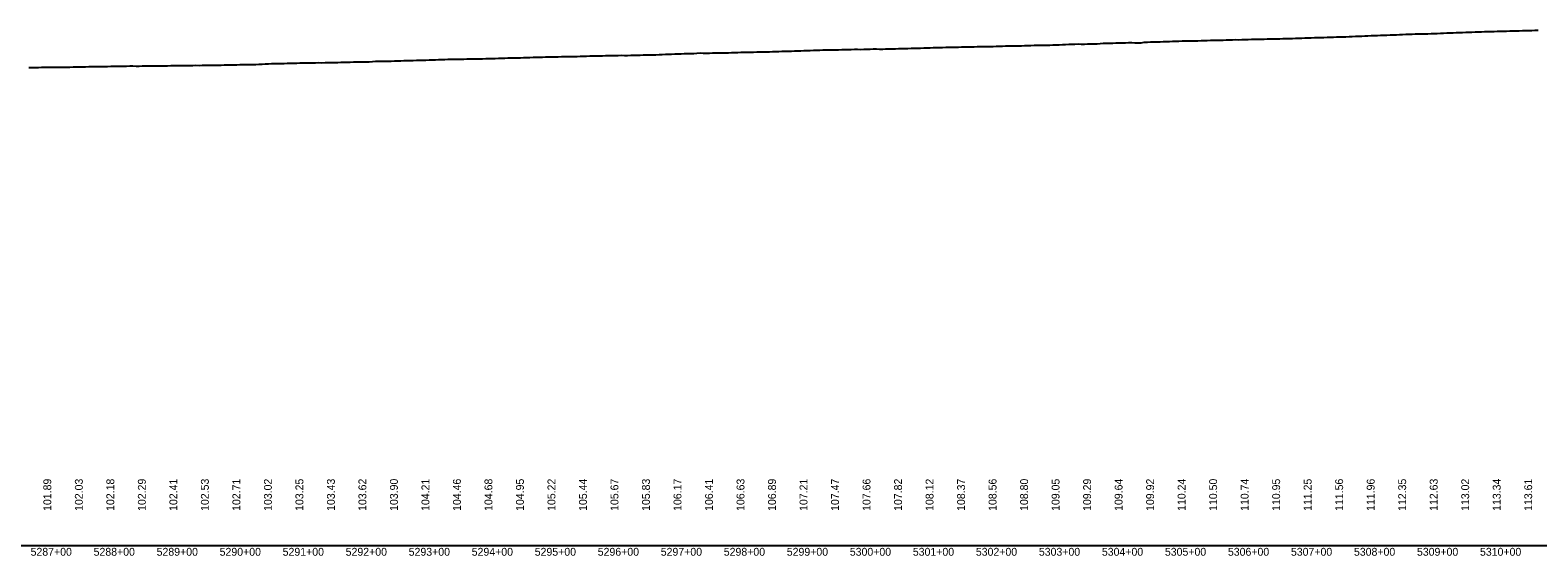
# Model space of a CAD drawing. Extents: x 2147288 to 2220488, y 740833 to 759333.
# Drawn here: x 2161047 to 2163439, y 758067 to 758902 of the extents above; entities that cross this region are included whole.
import ezdxf

# ---------------------------------------------------------------- set-up
doc = ezdxf.new("R2010")
doc.units = 0
for name, color, linetype in [('RD_DDB_Profile_EX', 7, 'Continuous'), ('RD_DDB_StaTX', 7, 'Continuous'), ('RD_DDB_StripGrade', 7, 'Continuous'), ('RD_GPK_Profile_Cell', 7, 'Continuous')]:
    doc.layers.add(name, color=color, linetype=linetype)

msp = doc.modelspace()

# ---------------------------------------------------------------- linework, layer by layer
at = {"layer": 'RD_DDB_Profile_EX'}
for points in [[(2162534.6, 758875.3), (2162539.6, 758875.4), (2162544.6, 758875.4), (2162549.6, 758875.5), (2162554.6, 758875.6), (2162559.6, 758875.8), (2162564.6, 758875.9), (2162569.6, 758875.9), (2162574.6, 758876), (2162579.6, 758876.2), (2162584.6, 758876.4), (2162589.6, 758876.4), (2162594.6, 758876.6), (2162599.6, 758876.7), (2162604.6, 758876.8), (2162609.6, 758876.8), (2162614.6, 758876.9), (2162619.6, 758877), (2162624.6, 758877.2), (2162629.6, 758877.4), (2162634.6, 758877.5), (2162639.6, 758877.6), (2162644.6, 758877.7), (2162649.6, 758877.8), (2162654.6, 758877.9), (2162659.6, 758878), (2162664.6, 758878.1), (2162669.6, 758878.3), (2162674.6, 758878.4), (2162679.6, 758878.6), (2162684.6, 758878.8), (2162689.6, 758879), (2162694.6, 758879.2), (2162699.6, 758879.4), (2162704.6, 758879.6), (2162709.6, 758879.8), (2162714.6, 758879.7), (2162719.6, 758879.7), (2162724.6, 758879.8), (2162729.6, 758879.8), (2162734.6, 758879.9), (2162739.6, 758880.1), (2162744.6, 758880.7), (2162749.6, 758881), (2162754.6, 758880.9), (2162759.6, 758881.1), (2162764.6, 758881.3), (2162769.6, 758881.4), (2162774.6, 758881.5), (2162779.6, 758881.6), (2162784.6, 758881.7), (2162789.6, 758882), (2162794.6, 758881.9), (2162799.6, 758881.7), (2162804.6, 758881.8), (2162809.6, 758881.8), (2162814.6, 758882.6), (2162819.6, 758882.7), (2162824.6, 758882.9), (2162829.6, 758883), (2162834.6, 758883.1), (2162839.6, 758883.3), (2162844.6, 758883.5), (2162849.6, 758883.7), (2162854.6, 758883.8), (2162859.6, 758884), (2162864.6, 758884.2), (2162869.6, 758884.3), (2162874.6, 758884.5), (2162879.6, 758884.6), (2162884.6, 758884.7), (2162889.6, 758884.8), (2162894.6, 758884.9), (2162899.6, 758885), (2162904.6, 758885.1), (2162909.6, 758885.2), (2162914.6, 758885.4), (2162919.6, 758885.6), (2162924.6, 758885.8), (2162929.6, 758885.9), (2162934.6, 758886), (2162939.6, 758886), (2162944.6, 758886.1), (2162949.6, 758886.2), (2162954.6, 758886.4), (2162959.6, 758886.6), (2162964.6, 758886.5), (2162969.6, 758886.8), (2162974.6, 758887), (2162979.6, 758887.1), (2162984.6, 758887.2), (2162989.6, 758887.2), (2162994.6, 758887.2), (2162999.6, 758887.3), (2163004.6, 758887.6), (2163009.6, 758887.7), (2163014.6, 758887.8), (2163019.6, 758887.9), (2163024.6, 758888), (2163029.6, 758888.1), (2163034.6, 758888.3)], [(2163034.6, 758888.3), (2163039.6, 758888.4), (2163044.6, 758888.6), (2163049.6, 758888.7), (2163054.6, 758888.9), (2163059.6, 758889), (2163064.6, 758889.1), (2163069.6, 758889.3), (2163074.6, 758889.4), (2163079.6, 758889.6), (2163084.6, 758889.8), (2163089.6, 758890.1), (2163094.6, 758890.1), (2163099.6, 758890.3), (2163104.6, 758890.4), (2163109.6, 758890.6), (2163114.6, 758890.7), (2163119.6, 758890.9), (2163124.6, 758891), (2163129.6, 758891.2), (2163134.6, 758891.3), (2163139.6, 758891.5), (2163144.6, 758891.7), (2163149.6, 758891.9), (2163154.6, 758891.9), (2163159.6, 758892), (2163164.6, 758892.6), (2163169.6, 758892.8), (2163174.6, 758893), (2163179.6, 758893.2), (2163184.6, 758893.4), (2163189.6, 758893.6), (2163194.6, 758893.8), (2163199.6, 758894), (2163204.6, 758894.2), (2163209.6, 758894.4), (2163214.6, 758894.5), (2163219.6, 758894.7), (2163224.6, 758894.9), (2163229.6, 758895.1), (2163234.6, 758895.3), (2163239.6, 758895.5), (2163244.6, 758895.6), (2163249.6, 758895.8), (2163254.6, 758895.9), (2163259.6, 758896), (2163264.6, 758896.1), (2163269.6, 758896.2), (2163274.6, 758896.3), (2163279.6, 758896.5), (2163284.6, 758896.7), (2163289.6, 758896.9), (2163294.6, 758897.2), (2163299.6, 758897.4), (2163304.6, 758897.6), (2163309.6, 758897.8), (2163314.6, 758897.9), (2163319.6, 758898.1), (2163324.6, 758898.3), (2163329.6, 758898.5), (2163334.6, 758898.7), (2163339.6, 758898.8), (2163344.6, 758899), (2163349.6, 758899.1), (2163354.6, 758899.4), (2163359.6, 758899.5), (2163364.6, 758899.6), (2163369.6, 758899.8), (2163374.6, 758900.1), (2163379.6, 758900.1), (2163384.6, 758900.2), (2163389.6, 758900.3), (2163394.6, 758900.5), (2163399.6, 758900.7), (2163404.6, 758900.7), (2163409.6, 758900.8), (2163414.6, 758900.9), (2163419.6, 758901.1), (2163424.6, 758901.2), (2163429.6, 758901.4), (2163434.6, 758901.6), (2163439.6, 758901.7)], [(2161534.6, 758850.6), (2161539.6, 758850.8), (2161544.6, 758850.9), (2161549.6, 758851), (2161554.6, 758851.1), (2161559.6, 758851.2), (2161564.6, 758851.2), (2161569.6, 758851.2), (2161574.6, 758851.3), (2161579.6, 758851.5), (2161584.6, 758851.6), (2161589.6, 758852.1), (2161594.6, 758852.2), (2161599.6, 758852.3), (2161604.6, 758852.4), (2161609.6, 758852.5), (2161614.6, 758852.6), (2161619.6, 758852.7), (2161624.6, 758852.8), (2161629.6, 758852.9), (2161634.6, 758853), (2161639.6, 758853.3), (2161644.6, 758853.4), (2161649.6, 758853.6), (2161654.6, 758853.7), (2161659.6, 758853.9), (2161664.6, 758854), (2161669.6, 758854.2), (2161674.6, 758854.3), (2161679.6, 758854.4), (2161684.6, 758854.6), (2161689.6, 758854.8), (2161694.6, 758854.9), (2161699.6, 758855.1), (2161704.6, 758855.3), (2161709.6, 758855.4), (2161714.6, 758855.4), (2161719.6, 758855.5), (2161724.6, 758855.6), (2161729.6, 758855.7), (2161734.6, 758855.8), (2161739.6, 758855.9), (2161744.6, 758856), (2161749.6, 758856), (2161754.6, 758856.1), (2161759.6, 758856.2), (2161764.6, 758856.3), (2161769.6, 758856.5), (2161774.6, 758856.6), (2161779.6, 758856.8), (2161784.6, 758856.9), (2161789.6, 758857.1), (2161794.6, 758857.2), (2161799.6, 758857.3), (2161804.6, 758857.5), (2161809.6, 758857.6), (2161814.6, 758857.7), (2161819.6, 758857.9), (2161824.6, 758858), (2161829.6, 758858.1), (2161834.6, 758858.3), (2161839.6, 758858.4), (2161844.6, 758858.6), (2161849.6, 758858.7), (2161854.6, 758858.9), (2161859.6, 758859), (2161864.6, 758859.2), (2161869.6, 758859.3), (2161874.6, 758859.4), (2161879.6, 758859.5), (2161884.6, 758859.6), (2161889.6, 758859.7), (2161894.6, 758859.7), (2161899.6, 758859.8), (2161904.6, 758859.9), (2161909.6, 758860), (2161914.6, 758860.1), (2161919.6, 758860.3), (2161924.6, 758860.5), (2161929.6, 758860.6), (2161934.6, 758860.7), (2161939.6, 758860.8), (2161944.6, 758860.9), (2161949.6, 758861), (2161954.6, 758861), (2161959.6, 758861.2), (2161964.6, 758861.4), (2161969.6, 758861.5), (2161974.6, 758861.6), (2161979.6, 758861.7), (2161984.6, 758861.9), (2161989.6, 758861.4), (2161994.6, 758861.7), (2161999.6, 758862), (2162004.6, 758862.2), (2162009.6, 758862.1), (2162014.6, 758862.2), (2162019.6, 758862.4), (2162024.6, 758862.5), (2162029.6, 758862.7), (2162034.6, 758862.4)], [(2162034.6, 758862.4), (2162039.6, 758862.6), (2162044.6, 758863.1), (2162049.6, 758863.3), (2162054.6, 758863.4), (2162059.6, 758863.6), (2162064.6, 758863.7), (2162069.6, 758863.9), (2162074.6, 758864.1), (2162079.6, 758864.2), (2162084.6, 758864.4), (2162089.6, 758864.5), (2162094.6, 758864.6), (2162099.6, 758864.8), (2162104.6, 758864.9), (2162109.6, 758865.5), (2162114.6, 758865.1), (2162119.6, 758865.2), (2162124.6, 758865.3), (2162129.6, 758865.5), (2162134.6, 758865.6), (2162139.6, 758865.7), (2162144.6, 758865.9), (2162149.6, 758865.9), (2162154.6, 758865.9), (2162159.6, 758866.1), (2162164.6, 758866.3), (2162169.6, 758866.4), (2162174.6, 758866.5), (2162179.6, 758866.6), (2162184.6, 758866.7), (2162189.6, 758866.8), (2162194.6, 758866.9), (2162199.6, 758867.1), (2162204.6, 758867.1), (2162209.6, 758867.2), (2162214.6, 758867.3), (2162219.6, 758867.4), (2162224.6, 758867.6), (2162229.6, 758867.8), (2162234.6, 758868), (2162239.6, 758868.1), (2162244.6, 758868.3), (2162249.6, 758868.4), (2162254.6, 758868.6), (2162259.6, 758868.8), (2162264.6, 758868.9), (2162269.6, 758869.1), (2162274.6, 758869.3), (2162279.6, 758869.4), (2162284.6, 758869.6), (2162289.6, 758869.7), (2162294.6, 758869.9), (2162299.6, 758870), (2162304.6, 758870.2), (2162309.6, 758870.3), (2162314.6, 758870.5), (2162319.6, 758870.6), (2162324.6, 758870.7), (2162329.6, 758870.7), (2162334.6, 758870.9), (2162339.6, 758870.9), (2162344.6, 758871), (2162349.6, 758871.1), (2162354.6, 758871.4), (2162359.6, 758871.5), (2162364.6, 758871.1), (2162369.6, 758871.3), (2162374.6, 758871.6), (2162379.6, 758871.7), (2162384.6, 758871.8), (2162389.6, 758872.1), (2162394.6, 758871.7), (2162399.6, 758871.3), (2162404.6, 758872.1), (2162409.6, 758872.1), (2162414.6, 758872.2), (2162419.6, 758872.2), (2162424.6, 758872.4), (2162429.6, 758872.6), (2162434.6, 758872.4), (2162439.6, 758872.7), (2162444.6, 758872.9), (2162449.6, 758873.1), (2162454.6, 758873.2), (2162459.6, 758873.3), (2162464.6, 758873.4), (2162469.6, 758873.6), (2162474.6, 758873.7), (2162479.6, 758874), (2162484.6, 758874.1), (2162489.6, 758874.3), (2162494.6, 758874.4), (2162499.6, 758874.6), (2162504.6, 758874.7), (2162509.6, 758874.8), (2162514.6, 758874.8), (2162519.6, 758874.9), (2162524.6, 758875.2), (2162529.6, 758875.2), (2162534.6, 758875.3)], [(2161044.6, 758842.5), (2161049.6, 758842.5), (2161054.6, 758842.5), (2161059.6, 758842.6), (2161064.6, 758842.8), (2161069.6, 758842.8), (2161074.6, 758842.8), (2161079.6, 758842.9), (2161084.6, 758842.9), (2161089.6, 758842.9), (2161094.6, 758842.9), (2161099.6, 758843), (2161104.6, 758843), (2161109.6, 758843.1), (2161114.6, 758843.3), (2161119.6, 758843.4), (2161124.6, 758843.5), (2161129.6, 758843.6), (2161134.6, 758843.7), (2161139.6, 758843.8), (2161144.6, 758843.9), (2161149.6, 758844), (2161154.6, 758844), (2161159.6, 758844.1), (2161164.6, 758844.2), (2161169.6, 758844.2), (2161174.6, 758844.3), (2161179.6, 758844.3), (2161184.6, 758844.3), (2161189.6, 758844.4), (2161194.6, 758844.5), (2161199.6, 758844.6), (2161204.6, 758844.8), (2161209.6, 758844.8), (2161214.6, 758844.7), (2161219.6, 758844.7), (2161224.6, 758844.8), (2161229.6, 758844.9), (2161234.6, 758844.9), (2161239.6, 758845), (2161244.6, 758845), (2161249.6, 758845.1), (2161254.6, 758845.2), (2161259.6, 758845.2), (2161264.6, 758845.3), (2161269.6, 758845.4), (2161274.6, 758845.4), (2161279.6, 758845.4), (2161284.6, 758845.5), (2161289.6, 758845.5), (2161294.6, 758845.6), (2161299.6, 758845.6), (2161304.6, 758845.7), (2161309.6, 758845.9), (2161314.6, 758845.8), (2161319.6, 758846), (2161324.6, 758846), (2161329.6, 758846.1), (2161334.6, 758846.1), (2161339.6, 758846), (2161344.6, 758846.1), (2161349.6, 758846.2), (2161354.6, 758846.4), (2161359.6, 758846.5), (2161364.6, 758846.6), (2161369.6, 758846.7), (2161374.6, 758846.8), (2161379.6, 758847), (2161384.6, 758847.1), (2161389.6, 758847.2), (2161394.6, 758847.4), (2161399.6, 758847.4), (2161404.6, 758847.3), (2161409.6, 758847.6), (2161414.6, 758847.9), (2161419.6, 758848.2), (2161424.6, 758848.4), (2161429.6, 758848.5), (2161434.6, 758848.6), (2161439.6, 758848.7), (2161444.6, 758848.8), (2161449.6, 758849), (2161454.6, 758849.1), (2161459.6, 758849.2), (2161464.6, 758849.3), (2161469.6, 758849.5), (2161474.6, 758849.6), (2161479.6, 758849.6), (2161484.6, 758849.7), (2161489.6, 758849.8), (2161494.6, 758849.8), (2161499.6, 758849.9), (2161504.6, 758850.1), (2161509.6, 758850), (2161514.6, 758850.2), (2161519.6, 758850.3), (2161524.6, 758850.4), (2161529.6, 758850.5), (2161534.6, 758850.6)]]:
    msp.add_lwpolyline(points, dxfattribs=at)
at = {"layer": 'RD_GPK_Profile_Cell'}
msp.add_line((2148888.3, 758083.4), (2165888.3, 758083.4), dxfattribs=at)

# ---------------------------------------------------------------- texts
at = {"layer": 'RD_DDB_StaTX'}
for s, p in [('5287+00', (2161047.3, 758067.2)), ('5288+00', (2161147.3, 758067.2)), ('5289+00', (2161247.3, 758067.2)), ('5290+00', (2161347.3, 758067.2)), ('5291+00', (2161447.3, 758067.2)), ('5292+00', (2161547.3, 758067.2)), ('5293+00', (2161647.3, 758067.2)), ('5294+00', (2161747.3, 758067.2)), ('5295+00', (2161847.3, 758067.2)), ('5296+00', (2161947.3, 758067.2)), ('5297+00', (2162047.3, 758067.2)), ('5298+00', (2162147.3, 758067.2)), ('5299+00', (2162247.3, 758067.2)), ('5300+00', (2162347.3, 758067.2)), ('5301+00', (2162447.3, 758067.2)), ('5302+00', (2162547.3, 758067.2)), ('5303+00', (2162647.3, 758067.2)), ('5304+00', (2162747.3, 758067.2)), ('5305+00', (2162847.3, 758067.2)), ('5306+00', (2162947.3, 758067.2)), ('5307+00', (2163047.3, 758067.2)), ('5308+00', (2163147.3, 758067.2)), ('5309+00', (2163247.3, 758067.2)), ('5310+00', (2163347.3, 758067.2))]:
    msp.add_text(s, height=12.5, dxfattribs=at).set_placement(p)
at = {"layer": 'RD_DDB_StripGrade'}
for s, p in [('101.89', (2161080.1, 758138.4)), ('102.03', (2161130.1, 758138.4)), ('102.18', (2161180.1, 758138.4)), ('102.29', (2161230.1, 758138.4)), ('102.41', (2161280.1, 758138.4)), ('102.53', (2161330.1, 758138.4)), ('102.71', (2161380.1, 758138.4)), ('103.02', (2161430.1, 758138.4)), ('103.25', (2161480.1, 758138.4)), ('103.43', (2161530.1, 758138.4)), ('103.62', (2161580.1, 758138.4)), ('103.90', (2161630.1, 758138.4)), ('104.21', (2161680.1, 758138.4)), ('104.46', (2161730.1, 758138.4)), ('104.68', (2161780.1, 758138.4)), ('104.95', (2161830.1, 758138.4)), ('105.22', (2161880.1, 758138.4)), ('105.44', (2161930.1, 758138.4)), ('105.67', (2161980.1, 758138.4)), ('105.83', (2162030.1, 758138.4)), ('106.17', (2162080.1, 758138.4)), ('106.41', (2162130.1, 758138.4)), ('106.63', (2162180.1, 758138.4)), ('106.89', (2162230.1, 758138.4)), ('107.21', (2162280.1, 758138.4)), ('107.47', (2162330.1, 758138.4)), ('107.66', (2162380.1, 758138.4)), ('107.82', (2162430.1, 758138.4)), ('108.12', (2162480.1, 758138.4)), ('108.37', (2162530.1, 758138.4)), ('108.56', (2162580.1, 758138.4)), ('108.80', (2162630.1, 758138.4)), ('109.05', (2162680.1, 758138.4)), ('109.29', (2162730.1, 758138.4)), ('109.64', (2162780.1, 758138.4)), ('109.92', (2162830.1, 758138.4)), ('110.24', (2162880.1, 758138.4)), ('110.50', (2162930.1, 758138.4)), ('110.74', (2162980.1, 758138.4)), ('110.95', (2163030.1, 758138.4)), ('111.25', (2163080.1, 758138.4)), ('111.56', (2163130.1, 758138.4)), ('111.96', (2163180.1, 758138.4)), ('112.35', (2163230.1, 758138.4)), ('112.63', (2163280.1, 758138.4)), ('113.02', (2163330.1, 758138.4)), ('113.34', (2163380.1, 758138.4)), ('113.61', (2163430.1, 758138.4))]:
    msp.add_text(s, height=12.5, rotation=90, dxfattribs=at).set_placement(p)

doc.saveas('drawing.dxf')
